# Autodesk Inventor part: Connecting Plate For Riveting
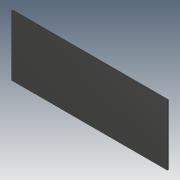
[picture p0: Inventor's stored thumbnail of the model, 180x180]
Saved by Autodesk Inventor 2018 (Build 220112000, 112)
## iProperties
Created: 2018-02
Part Number: Connecting Plate For Riveting
Material: Steel, Mild
Document SubType Name: Modeling
Designer: STK
Density: 7.85 g/cm^3
Appearance: Smooth - Black
Author: STK
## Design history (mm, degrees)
sketch "Sketch1"
  geometry: L1 (-457.2, -177.8)-(457.2, -177.8); L2 (457.2, -177.8)-(457.2, 177.8); L3 (457.2, 177.8)-(-457.2, 177.8); L4 (-457.2, 177.8)-(-457.2, -177.8); L5 (-457.2, -177.8)-(457.2, 177.8); L6 (457.2, -177.8)-(-457.2, 177.8); 1 further point
  constraints: 12 end point, 2 midpoint, 2 parallel, 1 horizontal, 1 perpendicular
  dimensions: "d0" = 914.4 distance of L3.end L2.end; "d1" = 355.6 distance of L2.end L1.end
extrude "Extrusion1" new body sketch "Sketch1" distance "d2" = 6.35; taper "d3" = 0 deg
body "Solid1"
